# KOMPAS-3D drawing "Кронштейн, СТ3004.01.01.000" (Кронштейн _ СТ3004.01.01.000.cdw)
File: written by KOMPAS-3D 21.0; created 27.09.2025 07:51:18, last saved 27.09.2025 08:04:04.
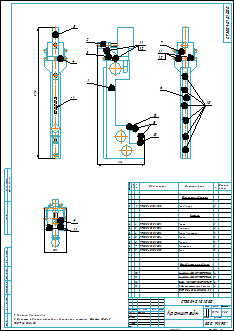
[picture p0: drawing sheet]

Sheet 1: A2, portrait

Document properties: Полное имя файла: C:\Users\Lutik\Yandex.Disk\Документы\Новая папка\Стапель №2\Стапель _ СТ3004.00.00.000\Опора _ СТ3004.01.00.000\2D\Кронштейн _ СТ3004.01.01.000\Кронштейн _ СТ3004.01.01.000.cdw; Масса: 11.762936

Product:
- Part/product: Кронштейн  | designation СТ3004.01.01.000
    Масса: 11.762936
  - Component [standard]: Гайка шестигранная низкая ГОСТ ISO 4035-М12-05-A2P  | qty 2  | pos. 13  | Материал: Сталь (density 1000 kg/m3); Масса: 0.001154; Раздел спецификации: Стандартные изделия; Рассекать на разрезах: no; additional columns: M12 - 05 - A2P
  - Component [assembly]: Основание  | designation СТ3004.01.01.100  | pos. 1  | Масса: 6.204975; Форматы листов документа: A3; source file: ..\..\3D\Кронштейн _ СТ3004.01.01.000\Основание _ СТ3004.01.01.100\Основание _ СТ3004.01.01.100.a3d, Основание _ СТ3004.01.01.100\Основание _ СТ3004.01.01.100.cdw
  - Component [detail]: Косынка  | designation СТ3003.01.01.002  | qty 2  | pos. 3  | Материал: Лист$dБ-ПН-НО-6 ГОСТ 19903-2015;Ст3сп ГОСТ 14637-89$ (density 7850 kg/m3); Масса: 0.116828; Форматы листов документа: A4; source file: ..\..\..\..\Стапель _ СТ3003.00.00.000\Опора _ СТ3003.01.00.000\3D\Кронштейн _ СТ3003.01.01.000\Косынка _ СТ3003.01.01.002.m3d
  - Component [detail]: Планка  | designation СТ3003.01.01.005  | pos. 6  | Материал: Сталь 45  ГОСТ 1050-2013 (density 7810 kg/m3); Масса: 1.670176; Форматы листов документа: A3; source file: ..\..\..\..\Стапель _ СТ3003.00.00.000\Опора _ СТ3003.01.00.000\2D\Кронштейн _ СТ3003.01.01.000\Планка _ СТ3003.01.01.005.cdw, ..\..\..\..\Стапель _ СТ3003.00.00.000\Опора _ СТ3003.01.00.000\3D\Кронштейн _ СТ3003.01.01.000\Планка _ СТ3003.01.01.005.m3d
  - Component [detail]: Опора  | designation СТ3003.01.01.004  | qty 2  | pos. 5  | Материал: Круг$d35 ГОСТ 2590-2006;Ст3сп ГОСТ 535-2005$ (density 7850 kg/m3); Масса: 0.078797; Форматы листов документа: A4; source file: ..\..\..\..\Стапель _ СТ3003.00.00.000\Опора _ СТ3003.01.00.000\2D\Кронштейн _ СТ3003.01.01.000\Опора _ СТ3003.01.01.004.cdw, ..\..\..\..\Стапель _ СТ3003.00.00.000\Опора _ СТ3003.01.00.000\3D\Кронштейн _ СТ3003.01.01.000\Опора _ СТ3003.01.01.004.m3d
  - Component [detail]: Винт  | designation СТ3003.01.01.001  | pos. 2  | Материал: Круг$d30 ГОСТ 2590-2006;Ст3сп ГОСТ 535-2005$ (density 7850 kg/m3); Масса: 0.311599; Форматы листов документа: A4; additional columns: 110; source file: ..\..\..\..\Стапель _ СТ3003.00.00.000\Опора _ СТ3003.01.00.000\2D\Кронштейн _ СТ3003.01.01.000\Винт _ СТ3003.01.01.001.cdw, ..\..\..\..\Стапель _ СТ3003.00.00.000\Опора _ СТ3003.01.00.000\3D\Кронштейн _ СТ3003.01.01.000\Винт _ СТ3003.01.01.001.m3d
  - Component [detail]: Упор  | designation СТ3004.01.01.001  | pos. 8  | Материал: Сталь 45  ГОСТ 1050-2013 (density 7810 kg/m3); Масса: 1.534235; Форматы листов документа: A3; source file: ..\..\3D\Кронштейн _ СТ3004.01.01.000\Упор _ СТ3004.01.01.001.m3d, Упор _ СТ3004.01.01.001.cdw
  - Component [standard]: Шайба A.8.01.10.019 ГОСТ 11371-78  | qty 6  | pos. 12  | Масса: 0.001828; Раздел спецификации: Стандартные изделия; Рассекать на разрезах: no
  - Component [standard]: Винт М8-6gx25.56.019 ГОСТ 11738-84  | qty 8  | pos. 11  | Материал: Сталь 30 ГОСТ 1050-2013 (density 1000 kg/m3); Масса: 0.01513; Раздел спецификации: Стандартные изделия; Рассекать на разрезах: no
  - Component [detail]: Пластина  | designation СТ3003.01.01.006  | pos. 7  | Материал: Лист$dБ-ПН-НО-16 ГОСТ 19903-2015;Ст3сп ГОСТ 14637-89$ (density 7850 kg/m3); Масса: 0.669577; Форматы листов документа: A4; source file: ..\..\..\..\Стапель _ СТ3003.00.00.000\Опора _ СТ3003.01.00.000\3D\Кронштейн _ СТ3003.01.01.000\Пластина _ СТ3003.01.01.006.m3d
  - Component [standard]: Винт М6-6gx20.56.019 ГОСТ 11738-84  | qty 6  | pos. 10  | Материал: Сталь 30 ГОСТ 1050-2013 (density 1000 kg/m3); Масса: 0.00666; Раздел спецификации: Стандартные изделия; Рассекать на разрезах: no
  - Component [detail]: Направляющая  | designation СТ3003.01.01.003  | pos. 4  | Материал: Сталь 45  ГОСТ 1050-2013 (density 7810 kg/m3); Масса: 0.806848; Форматы листов документа: A3; source file: ..\..\..\..\Стапель _ СТ3003.00.00.000\Опора _ СТ3003.01.00.000\3D\Кронштейн _ СТ3003.01.01.000\Направляющая _ СТ3003.01.01.003.m3d

Title block, sheet 1: Наименование: Кронштейн; designation: СТ3004.01.01.000; Масса: 11,76; Количество листов документа: 1; organisation: ООО "МИРО"; Форматы листов документа: A2; Разработал: Тимонин

Views: Вид 1, Спереди
Referenced files in C:\Users\Lutik\Yandex.Disk\Документы\Новая папка\Стапель №2\Стапель _ СТ3004.00.00.000\Опора _ СТ3004.01.00.000\3D\Кронштейн _ СТ3004.01.01.000\: Кронштейн _ СТ3004.01.01.000.a3d, Упор _ СТ3004.01.01.001.m3d
Referenced files in C:\Users\Lutik\Yandex.Disk\Документы\Новая папка\Стапель №2\Стапель _ СТ3003.00.00.000\Опора _ СТ3003.01.00.000\3D\Кронштейн _ СТ3003.01.01.000\: Направляющая _ СТ3003.01.01.003.m3d, Косынка _ СТ3003.01.01.002.m3d, Пластина _ СТ3003.01.01.006.m3d, Винт _ СТ3003.01.01.001.m3d, Опора _ СТ3003.01.01.004.m3d, Планка _ СТ3003.01.01.005.m3d
Referenced files in C:\Users\Lutik\Yandex.Disk\Документы\Новая папка\Стапель №2\Стапель _ СТ3003.00.00.000\Опора _ СТ3003.01.00.000\2D\Кронштейн _ СТ3003.01.01.000\: Винт _ СТ3003.01.01.001.cdw, Опора _ СТ3003.01.01.004.cdw, Планка _ СТ3003.01.01.005.cdw
Referenced files in C:\Users\Lutik\Yandex.Disk\Документы\Новая папка\Стапель №2\Стапель _ СТ3004.00.00.000\Опора _ СТ3004.01.00.000\3D\Кронштейн _ СТ3004.01.01.000\Основание _ СТ3004.01.01.100\: Основание _ СТ3004.01.01.100.a3d, Пластина _ СТ3004.01.01.101.m3d
Referenced files in C:\Users\Lutik\Yandex.Disk\Документы\Новая папка\Стапель №2\Стапель _ СТ3004.00.00.000\Опора _ СТ3004.01.00.000\2D\Кронштейн _ СТ3004.01.01.000\Основание _ СТ3004.01.01.100\: Основание _ СТ3004.01.01.100.cdw
Referenced files in C:\Users\Lutik\Yandex.Disk\Документы\Новая папка\Стапель №2\Стапель _ СТ3004.00.00.000\Опора _ СТ3004.01.00.000\2D\Кронштейн _ СТ3004.01.01.000\: Упор _ СТ3004.01.01.001.cdw
Referenced files in C:\Users\Lutik\Yandex.Disk\Документы\Новая папка\Стапель №2\Стапель _ СТ3003.00.00.000\Опора _ СТ3003.01.00.000\3D\Кронштейн _ СТ3003.01.01.000\Основание _ СТ3003.01.01.100\: Пластина _ СТ3003.01.01.102.m3d
Referenced files in C:\Program Files\ASCON\KOMPAS-3D v21\Libs\PARTLib\DATA\vault\Methods\Kompas\3D\: PLib_Washer_1_712.m3d, PLib_Nut_ISO_1100.m3d
Referenced files in C:\Program Files\ASCON\KOMPAS-3D v21\Libs\PartLib\DATA\VAULT\Methods\Kompas\3D\: PLib_Screw_GOST_11738_1500.m3d
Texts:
  Гайка шестигранная низкая ГОСТ ISO 4035-М12-05-A2P
  Гайка шестигранная низкая
  ГОСТ ISO
  Винт М6-6gx20.56.019 ГОСТ 11738-84
  Крепежное изделие ГОСТ
  Винт
  ГОСТ
  Винт М8-6gx25.56.019 ГОСТ 11738-84
  Шайба A.8.01.10.019 ГОСТ 11371-78
  Шайба
  СТ3003.01.01.003
  Направляющая
  СТ3003.01.01.002
  Косынка
  СТ3003.01.01.006
  Пластина
  СТ3003.01.01.001
  СТ3004.01.01.100
  Основание
  СТ3003.01.01.004
  Опора
  СТ3003.01.01.005
  Планка
  СТ3004.01.01.001
  Упор
  ГОСТ ISO 4035-М12-05-A2P
  СТ3004.01.00.000
  СТ3004.01.01.101
  СТ3004.01.01.101 Пластина
  СТ3003.01.01.102
  СТ3003.01.01.102 Пластина
  СТ3004.01.01.100 Основание
  СТ3003.01.01.003 Направляющая
  СТ3003.01.01.002 Косынка
  СТ3003.01.01.006 Пластина
  СТ3003.01.01.005 Планка
  СТ3003.01.01.004 Опора
  СТ3003.01.01.001 Винт
  СТ3004.01.01.001 Упор
  СТ3004.01.01.000 Кронштейн
Dimensions and other numbers on the sheet: 590; 4; 8; 05; 1; 56; 40Х; 019; 01; 10; 13; 2; 6; 11; 12; 3; 7; 5; 1:2,5; 11,76

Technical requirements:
  Размеры для справок.
  Нанести ударным способом обозначение чертежа. Шрифт 10-Пр3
